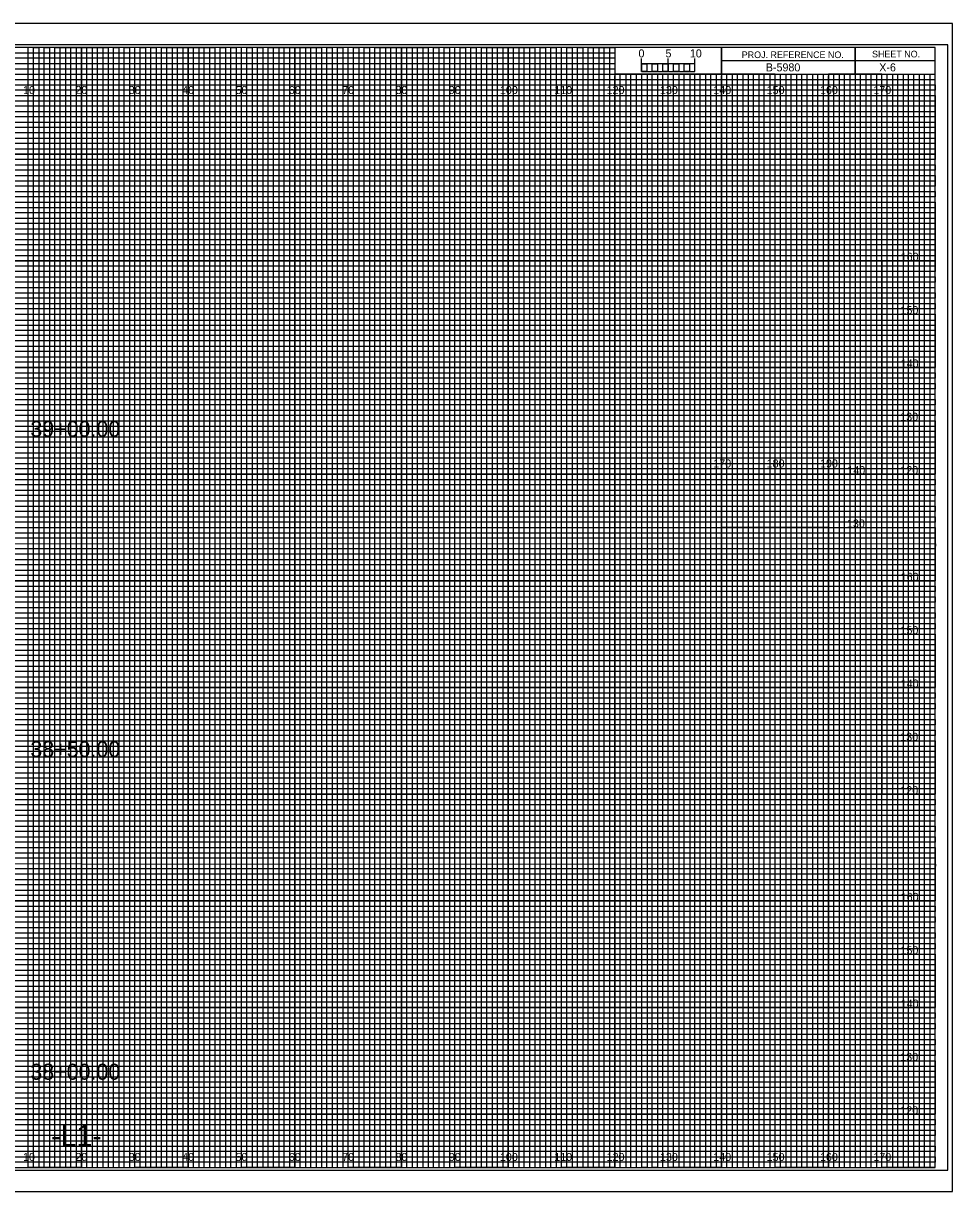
# Model space of a CAD drawing. Extents: x -13 to 323, y -5 to 3294.
# Drawn here: x 149.1 to 323.3, y 1095.5 to 1314.5 of the extents above; entities that cross this region are included whole.
import ezdxf

# ---------------------------------------------------------------- set-up
doc = ezdxf.new("R2010")
doc.units = 0
for name, color, linetype in [('Default', 7, 'Continuous'), ('Prop XS Alignment Label', 7, 'Continuous'), ('Prop XS Bar Scale Labels', 7, 'Continuous'), ('Prop XS Elevation Labels', 7, 'Continuous'), ('Prop XS Offset Labels', 7, 'Continuous'), ('Prop XS Project Number', 7, 'Continuous'), ('Prop XS Sheet Number', 7, 'Continuous'), ('Prop XS Station Labels', 7, 'Continuous'), ('Scratch_Level_0', 7, 'Continuous'), ('Sheet Cross Section CELL', 7, 'Continuous'), ('Sheet Cross Section Grid Major CELL', 7, 'Continuous'), ('Sheet Cross Section Grid Middle CELL', 7, 'Continuous'), ('Sheet Cross Section Grid Minor 1 CELL', 7, 'Continuous'), ('Sheet Cross Section Grid Minor 2 CELL', 7, 'Continuous'), ('Sheet Cross Section Scale CELL', 7, 'Continuous'), ('Sheet Cutting Line CELL', 7, 'Continuous'), ('Sheet DOT Grid CELL', 7, 'Continuous'), ('Sheet Plot Border Inside CELL', 7, 'Continuous'), ('Sheet Plot Border Outside CELL', 7, 'Continuous')]:
    doc.layers.add(name, color=color, linetype=linetype)

msp = doc.modelspace()

# ---------------------------------------------------------------- linework, layer by layer
at = {"layer": 'Default'}
msp.add_lwpolyline([(280, 1230), (300, 1230), (300, 1220), (280, 1220)], close=True, dxfattribs=at)
at = {"layer": 'Scratch_Level_0'}
for points in [[(2, 1270), (310, 1270), (310, 1230), (2, 1230)], [(-8, 1250), (300, 1250), (300, 1210), (-8, 1210)], [(10, 1210), (310, 1210), (310, 1170), (10, 1170)], [(10, 1150), (310, 1150), (310, 1110), (10, 1110)]]:
    msp.add_lwpolyline(points, close=True, dxfattribs=at)
at = {"layer": 'Sheet Cross Section CELL'}
for p, q in [((305, 1310), (305, 1305)), ((305, 1305), (305, 1310)), ((280, 1307.5), (280, 1305)), ((320, 1307.49), (280, 1307.49)), ((280, 1305), (320, 1305))]:
    msp.add_line(p, q, dxfattribs=at)
for points in [[(320, 1310), (0, 1310), (0, 1100), (320, 1100)], [(280, 1310), (260, 1310), (260, 1305.03), (280, 1305.03)], [(320, 1310), (280, 1310), (280, 1305), (320, 1305)]]:
    msp.add_lwpolyline(points, close=True, dxfattribs=at)
at = {"layer": 'Sheet Cross Section Grid Major CELL'}
for p, q in [((150, 1310), (140, 1310)), ((150, 1100), (150, 1310)), ((170, 1310), (160, 1310)), ((160, 1310), (160, 1100)), ((170, 1100), (170, 1310)), ((190, 1310), (180, 1310)), ((180, 1310), (180, 1100)), ((190, 1100), (190, 1310)), ((210, 1310), (200, 1310)), ((200, 1310), (200, 1100)), ((210, 1100), (210, 1310)), ((230, 1310), (220, 1310)), ((220, 1310), (220, 1100)), ((230, 1100), (230, 1310)), ((250, 1310), (240, 1310)), ((240, 1310), (240, 1100)), ((250, 1100), (250, 1310)), ((260, 1310), (260, 1100)), ((270, 1100), (270, 1305)), ((290, 1305), (280, 1305)), ((280, 1305), (280, 1100)), ((290, 1100), (290, 1305)), ((310, 1305), (300, 1305)), ((300, 1305), (300, 1100)), ((310, 1100), (310, 1305)), ((160, 1100), (150, 1100)), ((180, 1100), (170, 1100)), ((200, 1100), (190, 1100)), ((220, 1100), (210, 1100)), ((240, 1100), (230, 1100)), ((260, 1100), (250, 1100)), ((280, 1100), (270, 1100)), ((300, 1100), (290, 1100)), ((320, 1100), (310, 1100)), ((320, 1100), (320, 1100))]:
    msp.add_line(p, q, dxfattribs=at)
for points in [[(0, 1300), (320, 1300), (320, 1290), (0, 1290)], [(0, 1280), (320, 1280), (320, 1270), (0, 1270)], [(0, 1260), (320, 1260), (320, 1250), (0, 1250)], [(0, 1240), (320, 1240), (320, 1230), (0, 1230)], [(0, 1220), (320, 1220), (320, 1210), (0, 1210)], [(0, 1200), (320, 1200), (320, 1190), (0, 1190)], [(0, 1180), (320, 1180), (320, 1170), (0, 1170)], [(0, 1160), (320, 1160), (320, 1150), (0, 1150)], [(0, 1140), (320, 1140), (320, 1130), (0, 1130)], [(0, 1120), (320, 1120), (320, 1110), (0, 1110)]]:
    msp.add_lwpolyline(points, dxfattribs=at)
at = {"layer": 'Sheet Cross Section Grid Middle CELL'}
for points in [[(145, 1100), (155, 1100), (155, 1310), (165, 1310), (165, 1100), (175, 1100), (175, 1310), (185, 1310), (185, 1100), (195, 1100), (195, 1310), (205, 1310), (205, 1100), (215, 1100), (215, 1310), (225, 1310), (225, 1100), (235, 1100), (235, 1310), (245, 1310), (245, 1100), (255, 1100), (255, 1310), (259.93, 1310), (260, 1310), (260, 1305), (264.99, 1305), (264.99, 1100), (275, 1100), (275, 1305), (285, 1305), (285, 1100), (295, 1100), (295, 1305), (305, 1305), (305, 1100), (315, 1100), (315, 1305)], [(0, 1305), (275, 1305)], [(0, 1285), (320, 1285), (320, 1295), (0, 1295)], [(0, 1265), (320, 1265), (320, 1275), (0, 1275)], [(0, 1245), (320, 1245), (320, 1255), (0, 1255)], [(0, 1225), (320, 1225), (320, 1235), (0, 1235)], [(0, 1205), (320, 1205), (320, 1215), (0, 1215)], [(0, 1185), (320, 1185), (320, 1195), (0, 1195)], [(0, 1165), (320, 1165), (320, 1175), (0, 1175)], [(0, 1145), (320, 1145), (320, 1155), (0, 1155)], [(0, 1125), (320, 1125), (320, 1135), (0, 1135)], [(0, 1105), (320, 1105), (320, 1115), (0, 1115)]]:
    msp.add_lwpolyline(points, dxfattribs=at)
at = {"layer": 'Sheet Cross Section Grid Minor 1 CELL'}
for p, q in [((0, 1309), (260, 1309)), ((260, 1307.98), (0, 1307.98)), ((260, 1309), (260, 1307.98)), ((0, 1307), (260, 1307)), ((260, 1305.89), (0, 1305.89)), ((260, 1307), (260, 1305.89)), ((0, 1304), (320, 1304))]:
    msp.add_line(p, q, dxfattribs=at)
for points in [[(0, 1303), (270, 1303), (320, 1303), (320, 1302), (0, 1302)], [(0, 1301), (320, 1301), (320, 1299), (0, 1299)], [(0, 1298), (320, 1298), (320, 1297), (0, 1296.98)], [(0, 1296), (320, 1296), (320, 1294), (0, 1294)], [(0, 1293), (320, 1293), (320, 1292), (0, 1292)], [(0, 1291), (320, 1291), (320, 1289), (0, 1289)], [(0, 1288), (320, 1288), (320, 1287), (0, 1287)], [(0, 1286), (320, 1286), (320, 1284), (0, 1284)], [(0, 1283), (320, 1283), (320, 1282), (0, 1282)], [(0, 1281), (320, 1281), (320, 1279), (0, 1279)], [(0, 1278), (320, 1278), (320, 1277), (0, 1277)], [(0, 1276), (320, 1276), (320, 1273.95), (320, 1273), (320, 1272), (0, 1272)], [(0, 1274), (320, 1274), (320, 1273), (0, 1273)], [(0, 1271), (320, 1271), (320, 1269), (0, 1269.03)], [(0, 1269.03), (320, 1269), (320, 1268), (0, 1268)], [(0, 1267), (320, 1267), (320, 1266), (0, 1266)], [(0, 1264), (320, 1264), (320, 1263), (0, 1263)], [(0, 1262), (320, 1262), (320, 1261), (0, 1261)], [(-0.07, 1258.89), (320, 1258.89), (320, 1257.88), (-0.07, 1257.88)], [(0, 1257), (320, 1257), (320, 1256), (0, 1256)], [(0, 1254), (320, 1254), (320, 1253), (0, 1253)], [(0, 1252), (320, 1252), (320, 1251), (0, 1251)], [(0, 1249), (320, 1249), (320, 1248), (0, 1248)], [(0, 1247), (320, 1247), (320, 1246), (0, 1246)], [(0, 1244), (320, 1244), (320, 1243), (0, 1243)], [(0, 1242), (320, 1242), (320, 1241), (0, 1241)], [(0, 1239), (320, 1239), (319.99, 1237.98), (0, 1238)], [(0, 1237), (320, 1237), (320, 1236), (0, 1236)], [(0, 1234), (320, 1234), (320, 1233), (0, 1233)], [(0, 1232), (320, 1232), (320, 1231), (0, 1231)], [(0, 1229), (320, 1229), (320, 1228), (0, 1228)], [(0, 1227), (320, 1227), (320, 1226), (0, 1226)], [(0, 1224), (320, 1224), (320, 1223), (0, 1223)], [(0, 1222), (320, 1222), (320, 1221), (0, 1221)], [(0, 1219), (320, 1219), (320, 1218), (0, 1218)], [(0, 1216.99), (320.07, 1216.91), (320, 1216), (0, 1216)], [(0, 1214), (320, 1214), (320, 1213), (0, 1213)], [(0, 1212), (320, 1212), (320, 1211), (0, 1211)], [(0, 1209), (320, 1209), (320, 1208), (0, 1208)], [(0, 1207), (320, 1207), (320, 1206), (0, 1206)], [(0, 1204), (320, 1204), (320, 1203), (0, 1203)], [(0, 1202), (320, 1202), (320, 1201), (0, 1201)], [(0, 1199), (320, 1199), (320, 1198), (0, 1198)], [(0, 1197), (320, 1197), (320, 1196), (0, 1196)], [(0, 1194), (320, 1194), (320, 1193), (0, 1193)], [(0, 1192), (320, 1192), (320, 1191), (0, 1191)], [(0, 1189), (320, 1189), (320, 1188), (0, 1188)], [(0, 1187), (320, 1187), (320, 1186), (0, 1186)], [(0, 1184), (320, 1184), (320, 1183), (0, 1183)], [(0, 1182), (320, 1182), (320, 1181), (0, 1181)], [(0, 1179), (320, 1179), (319.99, 1177.98), (0, 1178)], [(0, 1177), (320, 1177), (320, 1176), (0, 1176)], [(0, 1174), (320, 1174), (320, 1173), (0, 1173)], [(0, 1172), (320, 1172), (320, 1171), (0, 1171)], [(0, 1169), (320, 1169), (320, 1168), (0, 1168)], [(0, 1167), (320, 1167), (320, 1166), (0, 1166)], [(0, 1164), (320, 1164), (320, 1163), (0, 1163)], [(0, 1162), (320, 1162), (320, 1161), (0, 1161)], [(0, 1159), (320, 1159), (320, 1158), (0, 1158)], [(0, 1156.99), (320.07, 1156.91), (320, 1156), (0, 1156)], [(0, 1154), (320, 1154), (320, 1153), (0, 1153)], [(0, 1152), (320, 1152), (320, 1151), (0, 1151)], [(0, 1149), (320, 1149), (320, 1148), (0, 1148)], [(0, 1147), (320, 1147), (320, 1146), (0, 1146)], [(0, 1144), (320, 1144), (320, 1143), (0, 1143)], [(0, 1142), (320, 1142), (320, 1141), (0, 1141)], [(0, 1139), (320, 1139), (320, 1138), (0, 1138)], [(0, 1137), (320, 1137), (320, 1136), (0, 1136)], [(0, 1134), (320, 1134), (320, 1133), (0, 1133)], [(0, 1132), (320, 1132), (320, 1131), (0, 1131)], [(0, 1129), (320, 1129), (320, 1128), (0, 1128)], [(0, 1127), (320, 1127), (320, 1126), (0, 1126)], [(0, 1124), (320, 1124), (320, 1123), (0, 1123)], [(0, 1122), (320, 1122), (320, 1121), (0, 1121)], [(0, 1119), (320, 1119), (320, 1118), (0, 1118)], [(0, 1117), (320, 1117), (320, 1116), (0, 1116)], [(0, 1114), (320, 1114), (320, 1113), (0, 1113)], [(0, 1112), (320, 1112), (320, 1111), (0, 1111)], [(0, 1109), (320, 1109), (320, 1108), (0, 1108)], [(0, 1107), (320, 1107), (320, 1106), (0, 1106)], [(0, 1104), (320, 1104), (320, 1103), (0, 1103)], [(0, 1102), (320, 1102), (320, 1101), (0, 1101)]]:
    msp.add_lwpolyline(points, dxfattribs=at)
at = {"layer": 'Sheet Cross Section Grid Minor 2 CELL'}
for p, q in [((267, 1305), (266.01, 1305)), ((266.01, 1305), (266.01, 1100)), ((267, 1100), (267, 1305)), ((269, 1305), (268, 1305)), ((268, 1305), (268, 1100)), ((269, 1100), (269, 1305)), ((266.01, 1100), (265, 1100)), ((268, 1100), (267, 1100))]:
    msp.add_line(p, q, dxfattribs=at)
for points in [[(150, 1100), (151, 1100), (151, 1310), (152, 1310), (152, 1100)], [(152, 1100), (153, 1100), (153, 1310), (154, 1310), (154, 1100)], [(155, 1100), (156, 1100), (156, 1310), (157, 1310), (157, 1100)], [(157, 1100), (158, 1100), (158, 1310), (159, 1310), (159, 1100)], [(160, 1100), (161, 1100), (161, 1310), (162, 1310), (162, 1100)], [(162, 1100), (163, 1100), (163, 1310), (164, 1310), (164, 1100)], [(165, 1100), (166, 1100), (166, 1310), (167, 1310), (167, 1100)], [(167, 1100), (168, 1100), (168, 1310), (169, 1310), (169, 1100)], [(170, 1100), (171, 1100), (171, 1310), (172, 1310), (172, 1100)], [(172, 1100), (173, 1100), (173, 1310), (174, 1310), (174, 1100)], [(175, 1100), (176, 1100), (176, 1310), (177, 1310), (177, 1100)], [(177, 1100), (178, 1100), (178, 1310), (179, 1310), (179, 1100)], [(180, 1100), (181, 1100), (181, 1310), (182, 1310), (182, 1100)], [(182, 1100), (183, 1100), (183, 1310), (184, 1310), (184, 1100)], [(185, 1100), (186, 1100), (186, 1310), (187, 1310), (187, 1100)], [(187, 1100), (188, 1100), (188, 1310), (189, 1310), (189, 1100)], [(190, 1100), (191, 1100), (191, 1310), (192, 1310), (192, 1100)], [(192, 1100), (193, 1100), (193, 1310), (194, 1310), (194, 1100)], [(195, 1100), (196, 1100), (196, 1310), (197, 1310), (197, 1100)], [(197, 1100), (198, 1100), (198, 1310), (199, 1310), (199, 1100)], [(200, 1100), (201, 1100), (201, 1310), (202, 1310), (202, 1100)], [(202, 1100), (203, 1100), (203, 1310), (204, 1310), (204, 1100)], [(205, 1100), (206, 1100), (206, 1310), (207, 1310), (207, 1100)], [(207, 1100), (208, 1100), (208, 1310), (209, 1310), (209, 1100)], [(210, 1100), (211, 1100), (211, 1310), (212, 1310), (212, 1100)], [(212, 1100), (213, 1100), (213, 1310), (214, 1310), (214, 1100)], [(215, 1100), (216, 1100), (216, 1310), (217, 1310), (217, 1100)], [(217, 1100), (218, 1100), (218, 1310), (219, 1310), (219, 1100)], [(220, 1100), (221, 1100), (221, 1310), (222, 1310), (222, 1100)], [(222, 1100), (223, 1100), (223, 1310), (224, 1310), (224, 1100)], [(225, 1100), (226, 1100), (226, 1310), (227, 1310), (227, 1100)], [(227, 1100), (228, 1100), (228, 1310), (229, 1310), (229, 1100)], [(230, 1100), (231, 1100), (231, 1310), (232, 1310), (232, 1100)], [(232, 1100), (233, 1100), (233, 1310), (234, 1310), (234, 1100)], [(235, 1100), (236, 1100), (236, 1310), (237, 1310), (237, 1100)], [(237, 1100), (238, 1100), (238, 1310), (239, 1310), (239, 1100)], [(240, 1100), (241, 1100), (241, 1310), (242, 1310), (242, 1100)], [(242, 1100), (243, 1100), (243, 1310), (244, 1310), (244, 1100)], [(245, 1100), (246, 1100), (246, 1310), (247, 1310), (247, 1100)], [(247, 1100), (248, 1100), (248, 1310), (249, 1310), (249, 1100)], [(250, 1100), (251, 1100), (251, 1310), (252, 1310), (252, 1100)], [(252, 1100), (253, 1100), (253, 1310), (254, 1310), (254, 1100)], [(255, 1100), (256, 1100), (256, 1310), (257, 1310), (257, 1100)], [(257, 1100), (258, 1100), (258, 1310), (259, 1310), (259, 1100)], [(260, 1100), (261, 1100), (261, 1305), (262.02, 1305), (262.02, 1100)], [(262, 1100), (263, 1100), (263, 1305), (263.99, 1305), (263.99, 1100)], [(270, 1100), (270.98, 1100), (270.98, 1305), (272, 1305), (272, 1100)], [(272, 1100), (273, 1100), (273, 1305), (274.05, 1305), (274.05, 1100)], [(275, 1100), (276, 1100), (276, 1305), (277, 1305), (277, 1100)], [(277, 1100), (278, 1100), (278, 1305), (279, 1305), (279, 1100)], [(280, 1100), (281, 1100), (281, 1305), (282, 1305), (282, 1100)], [(282, 1100), (283, 1100), (283, 1305), (284, 1305), (284, 1100)], [(285, 1100), (286, 1100), (286, 1305), (287, 1305), (287, 1100)], [(287, 1100), (288, 1100), (288, 1305), (289, 1305), (289, 1100)], [(290, 1100), (291, 1100), (291, 1305), (292, 1305), (292, 1100)], [(292, 1100), (293, 1100), (293, 1305), (294, 1305), (294, 1100)], [(295, 1100), (296, 1100), (296, 1305), (297, 1305), (297, 1100)], [(297, 1100), (298, 1100), (298, 1305), (299, 1305), (299, 1100)], [(300, 1100), (301, 1100), (301, 1305), (302, 1305), (302, 1100)], [(302, 1100), (303, 1100), (303, 1305), (304, 1305), (304, 1100)], [(305, 1100), (306, 1100), (306, 1305), (307, 1305), (307, 1100)], [(307, 1100), (308, 1100), (308, 1305), (309, 1305), (309, 1100)], [(310, 1100), (311, 1100), (311, 1305), (312, 1305), (312, 1100)], [(312, 1100), (313, 1100), (313, 1305), (314, 1305), (314, 1100)], [(315, 1100), (316, 1100), (316, 1305), (317, 1305), (317, 1100)], [(317, 1100), (318, 1100), (318, 1305), (319, 1305), (319, 1100)]]:
    msp.add_lwpolyline(points, dxfattribs=at)
at = {"layer": 'Sheet Cross Section Scale CELL'}
for p, q in [((265, 1305.49), (265, 1307.9)), ((265, 1306.9), (265, 1307.9)), ((270, 1305.49), (270, 1307.9)), ((275, 1305.49), (275, 1307.9)), ((275, 1306.9), (275, 1307.9))]:
    msp.add_line(p, q, dxfattribs=at)
for points in [[(275, 1306.9), (265, 1306.9), (265, 1305.49), (275, 1305.49)], [(265, 1306.9), (266, 1306.9), (266, 1305.49), (265, 1305.49)], [(267, 1306.9), (268, 1306.9), (268, 1305.49), (267, 1305.49)], [(269, 1306.9), (270, 1306.9), (270, 1305.49), (269, 1305.49)], [(271, 1306.9), (272, 1306.9), (272, 1305.49), (271, 1305.49)], [(273, 1306.9), (274, 1306.9), (274, 1305.49), (273, 1305.49)]]:
    msp.add_lwpolyline(points, close=True, dxfattribs=at)
at = {"layer": 'Sheet Cutting Line CELL'}
for p, q in [((323.3, 1314.5), (-13.4, 1314.5)), ((-13.4, 1095.5), (323.3, 1095.5))]:
    msp.add_line(p, q, dxfattribs=at)
at = {"layer": 'Sheet DOT Grid CELL'}
for p, q in [((150, 1100), (150, 1310)), ((160, 1100), (160, 1310)), ((170, 1100), (170, 1310)), ((180, 1100), (180, 1310)), ((190, 1100), (190, 1310)), ((200, 1100), (200, 1310)), ((210, 1100), (210, 1310)), ((220, 1100), (220, 1310)), ((230, 1100), (230, 1310)), ((240, 1100), (240, 1310)), ((250, 1100), (250, 1310)), ((260, 1100), (260, 1304.69)), ((270, 1100), (270, 1304.69)), ((280, 1100), (280, 1304.69)), ((290, 1100), (290, 1304.69)), ((300, 1100), (300, 1304.69)), ((310, 1100), (310, 1304.69)), ((0, 1300), (320, 1300)), ((0, 1290), (320, 1290)), ((0, 1280), (320, 1280)), ((0, 1270), (320, 1270)), ((0, 1260), (320, 1260)), ((0, 1250), (320, 1250)), ((0, 1240), (320, 1240)), ((0, 1230), (320, 1230)), ((0, 1220), (320, 1220)), ((0, 1210), (320, 1210)), ((0, 1200), (320, 1200)), ((0, 1190), (320, 1190)), ((0, 1180), (320, 1180)), ((0, 1170), (320, 1170)), ((0, 1160), (320, 1160)), ((0, 1150), (320, 1150)), ((0, 1140), (320, 1140)), ((0, 1130), (320, 1130)), ((0, 1120), (320, 1120)), ((0, 1110), (320, 1110))]:
    msp.add_line(p, q, dxfattribs=at)
at = {"layer": 'Sheet Plot Border Inside CELL'}
msp.add_lwpolyline([(-10.8, 1099.5), (322.4, 1099.5), (322.4, 1310.5), (-10.8, 1310.5)], close=True, dxfattribs=at)
at = {"layer": 'Sheet Plot Border Outside CELL'}
msp.add_lwpolyline([(-13.4, 1095.5), (323.3, 1095.5), (323.3, 1314.5), (-13.4, 1314.5)], close=True, dxfattribs=at)

# ---------------------------------------------------------------- texts
at = {"layer": 'Prop XS Alignment Label'}
msp.add_text('-L1-', height=4, dxfattribs=at).set_placement((154.28, 1104))
at = {"layer": 'Prop XS Bar Scale Labels'}
for s, p in [('5', (269.47, 1308.12)), ('10', (274.04, 1308.12))]:
    msp.add_text(s, height=1.5, dxfattribs=at).set_placement(p)
at = {"layer": 'Prop XS Elevation Labels'}
for s, p in [('160', (313.57, 1270)), ('150', (313.52, 1260)), ('140', (313.57, 1250)), ('130', (313.49, 1240)), ('140', (303.57, 1230)), ('120', (313.5, 1230)), ('130', (303.49, 1220)), ('160', (313.57, 1210)), ('150', (313.52, 1200)), ('140', (313.57, 1190)), ('130', (313.49, 1180)), ('120', (313.5, 1170)), ('160', (313.57, 1150)), ('150', (313.52, 1140)), ('140', (313.57, 1130)), ('130', (313.49, 1120)), ('120', (313.5, 1110))]:
    msp.add_text(s, height=1.5, dxfattribs=at).set_placement(p)
at = {"layer": 'Prop XS Offset Labels'}
for s, p in [('10', (149.04, 1301.25)), ('20', (158.86, 1301.25)), ('30', (168.86, 1301.25)), ('40', (178.86, 1301.25)), ('50', (188.86, 1301.25)), ('60', (198.86, 1301.25)), ('70', (208.86, 1301.25)), ('80', (218.86, 1301.25)), ('90', (228.86, 1301.25)), ('100', (238.44, 1301.25)), ('110', (248.62, 1301.25)), ('120', (258.44, 1301.25)), ('130', (268.44, 1301.25)), ('140', (278.44, 1301.25)), ('150', (288.44, 1301.25)), ('160', (298.44, 1301.25)), ('170', (308.44, 1301.25)), ('170', (278.44, 1231.25)), ('180', (288.44, 1231.25)), ('190', (298.44, 1231.25)), ('10', (149.04, 1101.25)), ('20', (158.86, 1101.25)), ('30', (168.86, 1101.25)), ('40', (178.86, 1101.25)), ('50', (188.86, 1101.25)), ('60', (198.86, 1101.25)), ('70', (208.86, 1101.25)), ('80', (218.86, 1101.25)), ('90', (228.86, 1101.25)), ('100', (238.44, 1101.25)), ('110', (248.62, 1101.25)), ('120', (258.44, 1101.25)), ('130', (268.44, 1101.25)), ('140', (278.44, 1101.25)), ('150', (288.44, 1101.25)), ('160', (298.44, 1101.25)), ('170', (308.44, 1101.25))]:
    msp.add_text(s, height=1.5, dxfattribs=at).set_placement(p)
at = {"layer": 'Prop XS Project Number'}
msp.add_text('B-5980', height=1.5, dxfattribs=at).set_placement((288.28, 1305.5))
at = {"layer": 'Prop XS Sheet Number'}
msp.add_text('X-6', height=1.5, dxfattribs=at).set_placement((309.54, 1305.5))
at = {"layer": 'Prop XS Station Labels'}
for s, p in [('39+00.00', (150.41, 1236.98)), ('38+50.00', (150.41, 1176.95)), ('38+00.00', (150.41, 1116.48))]:
    msp.add_text(s, height=3, dxfattribs=at).set_placement(p)
at = {"layer": 'Sheet Cross Section CELL'}
for s, p in [('PROJ. REFERENCE NO.', (283.77, 1307.99)), ('SHEET NO.', (308.19, 1308.12))]:
    msp.add_text(s, height=1.25, dxfattribs=at).set_placement(p)
at = {"layer": 'Sheet Cross Section Scale CELL'}
msp.add_text('0', height=1.5, dxfattribs=at).set_placement((264.41, 1308.12))

doc.saveas('drawing.dxf')
